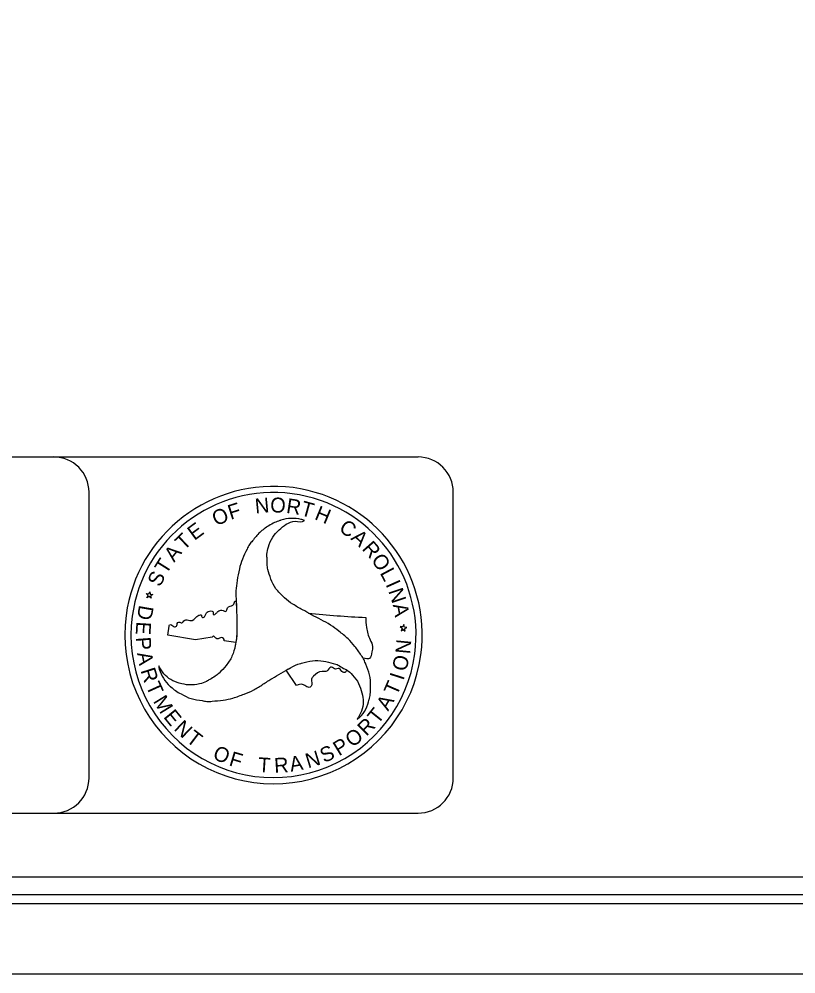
# Model space of a CAD drawing. Extents: x 2046816 to 2049224, y 578750 to 586986.
# Drawn here: x 2048068.9 to 2048289.2, y 585890.8 to 586161.6 of the extents above; entities that cross this region are included whole.
import ezdxf

# ---------------------------------------------------------------- set-up
doc = ezdxf.new("R2010")
doc.units = 0
for name, color, linetype in [('Sheet Plot Border Inside CELL', 7, 'Continuous'), ('Sheet Plot Border Outside CELL', 7, 'Continuous'), ('Sheet Title CELL', 7, 'Continuous')]:
    doc.layers.add(name, color=color, linetype=linetype)

msp = doc.modelspace()

# ---------------------------------------------------------------- linework, layer by layer
at = {"layer": 'Sheet Plot Border Inside CELL'}
msp.add_lwpolyline([(2047553.67, 585910.81), (2049219.66, 585910.81), (2049219.66, 586965.81), (2047553.67, 586965.81)], close=True, dxfattribs=at)
at = {"layer": 'Sheet Plot Border Outside CELL'}
msp.add_lwpolyline([(2049224.17, 586985.81), (2047540.67, 586985.81), (2047540.67, 585890.81), (2049224.17, 585890.81)], close=True, dxfattribs=at)
at = {"layer": 'Sheet Title CELL'}
for p, q in [((2047791.37, 586037.41), (2048182.04, 586037.41)), ((2048088.74, 585946.39), (2048088.74, 586027.41)), ((2048192.04, 585946.39), (2048192.04, 586027.41)), ((2048149.88, 586019.43), (2048149.8, 586019.35)), ((2048149.88, 586019.43), (2048149.8, 586019.35)), ((2048105.46, 585998.15), (2048104.94, 585998.66)), ((2048104.94, 585998.66), (2048105.67, 585998.56)), ((2048105.16, 585997.48), (2048105.46, 585998.15)), ((2048105.77, 585997.84), (2048105.16, 585997.48)), ((2048105.67, 585998.56), (2048105.96, 585999.2)), ((2048106.31, 585997.33), (2048105.77, 585997.84)), ((2048105.96, 585999.2), (2048106.11, 585998.5)), ((2048106.11, 585998.5), (2048106.83, 585998.41)), ((2048106.83, 585998.41), (2048106.18, 585998.05)), ((2048106.18, 585998.05), (2048106.31, 585997.33)), ((2048150.94, 585993.16), (2048150.94, 585993.16)), ((2048111.06, 585986.89), (2048111.48, 585989.39)), ((2048177.72, 585989.22), (2048177, 585989.31)), ((2048177, 585989.31), (2048177.54, 585988.81)), ((2048178.03, 585989.85), (2048177.72, 585989.22)), ((2048178.19, 585989.15), (2048178.03, 585989.85)), ((2048178.9, 585989.08), (2048178.19, 585989.15)), ((2048178.25, 585988.71), (2048178.9, 585989.08)), ((2048118.95, 585985.53), (2048111.06, 585986.89)), ((2048123.68, 585986.27), (2048118.95, 585985.53)), ((2048177.54, 585988.81), (2048177.23, 585988.14)), ((2048177.23, 585988.14), (2048177.85, 585988.49)), ((2048177.85, 585988.49), (2048178.37, 585987.99)), ((2048178.37, 585987.99), (2048178.25, 585988.71)), ((2048130.41, 585984.8), (2048127.1, 585985.28)), ((2048182.85, 585981.34), (2048182.85, 585981.34)), ((2048147.6, 585972.64), (2048144.6, 585976.91)), ((2048144.6, 585976.91), (2048144.6, 585976.91)), ((2047791.37, 585936.39), (2048182.04, 585936.39)), ((2047772.18, 585918.31), (2049192.16, 585918.31))]:
    msp.add_line(p, q, dxfattribs=at)
msp.add_lwpolyline([(2047722.16, 585913.31), (2049192.16, 585913.31)], dxfattribs=at)
for centre, radius, start, end in [((2048078.74, 586027.41), 10, 0, 90), ((2048182.04, 586027.41), 10, 360, 90), ((2048141.05, 585986.9), 42.17, 352.4211, 172.4211), ((2048141.05, 585986.9), 40.42, 352.4211, 172.4211), ((2048175.96, 586214.1), 222.36, 258.0996, 258.1992), ((2048141.05, 585986.9), 42.17, 172.4211, 352.4211), ((2048141.05, 585986.9), 40.42, 172.4211, 352.4211), ((2048175.96, 586214.1), 222.36, 263.5387, 267.7447), ((2048078.74, 585946.39), 10, 270, 360), ((2048182.04, 585946.39), 10, 270, 360)]:
    msp.add_arc(centre, radius, start, end, dxfattribs=at)
for points in [[(2048149.8, 586019.35), (2048148.89, 586019.72), (2048146.1, 586019.98), (2048143.15, 586019.45), (2048142.89, 586019.35), (2048141.37, 586018.79), (2048139.73, 586017.88), (2048137.17, 586016.03), (2048135.09, 586013.63), (2048134.24, 586012.59), (2048133.55, 586011.27), (2048132.23, 586008.44), (2048131.37, 586005.66), (2048130.74, 586002.35), (2048130.4, 585999.42), (2048130.48, 585996.37), (2048130.6, 585993.29), (2048130.65, 585990.31), (2048130.66, 585987.24), (2048130.27, 585984.25), (2048130.22, 585984), (2048129.27, 585980.88), (2048127.61, 585978.27), (2048125.64, 585976.14), (2048124.51, 585975.2), (2048122.97, 585974.29), (2048122.09, 585973.77), (2048120.07, 585973.05), (2048117.12, 585972.76), (2048114.34, 585973.3), (2048111.94, 585974.26), (2048109.95, 585975.95), (2048108.49, 585978.19)], [(2048164.82, 585963.01), (2048165.56, 585963.6), (2048167.2, 585965.89), (2048168.21, 585968.7), (2048168.29, 585968.98), (2048168.53, 585970.58), (2048168.57, 585972.48), (2048168.28, 585975.6), (2048167.2, 585978.6), (2048166.75, 585979.85), (2048165.93, 585981.14), (2048164.15, 585983.68), (2048162.18, 585985.82), (2048159.62, 585988), (2048157.24, 585989.74), (2048154.55, 585991.24), (2048151.84, 585992.66), (2048149.26, 585994.1), (2048146.55, 585995.64), (2048144.18, 585997.46), (2048144, 585997.65), (2048141.74, 586000.04), (2048140.32, 586002.79), (2048139.45, 586005.54), (2048139.23, 586006.97), (2048139.22, 586008.78), (2048139.17, 586009.82), (2048139.6, 586011.9), (2048140.82, 586014.63), (2048142.65, 586016.74), (2048144.69, 586018.32), (2048147.17, 586019.21), (2048149.8, 586019.35), (2048149.88, 586019.43)], [(2048111.48, 585989.39), (2048111.43, 585989.64), (2048111.89, 585989.85), (2048113, 585989.21), (2048113.66, 585989.64), (2048113.71, 585990.15), (2048114.24, 585990.6), (2048115.03, 585990.33), (2048115.88, 585991.16), (2048116.57, 585991.23), (2048117.99, 585991.05), (2048119.88, 585992.51), (2048120.6, 585992.51), (2048120.72, 585992.05), (2048121.14, 585991.9), (2048122.04, 585993.19), (2048122.25, 585993.37), (2048123.64, 585993.71), (2048123.95, 585993.42), (2048123.97, 585992.79), (2048124.14, 585992.64), (2048124.61, 585992.89), (2048125.29, 585993.55), (2048126.44, 585993.97), (2048127.65, 585993.66), (2048128, 585994.63), (2048129.56, 585995.41), (2048129.94, 585995.95), (2048130.09, 585996.54)], [(2048130.48, 585996.45), (2048130.48, 585996.37), (2048130.6, 585993.29), (2048130.65, 585990.31), (2048130.66, 585987.24), (2048130.4, 585984.81)], [(2048166.5, 585980.34), (2048165.93, 585981.14), (2048164.15, 585983.68), (2048162.18, 585985.82), (2048159.62, 585988), (2048157.24, 585989.74), (2048154.55, 585991.24), (2048151.84, 585992.66), (2048150.94, 585993.16)], [(2048167.2, 585991.91), (2048167.43, 585989.05), (2048168.45, 585985.57), (2048169.16, 585983.65), (2048168.93, 585982.1), (2048168.32, 585980.3), (2048166.51, 585980.35)], [(2048127.1, 585985.28), (2048126.86, 585985.93), (2048126.24, 585986.2), (2048125.32, 585985.86), (2048124.66, 585985.98), (2048124.01, 585986.6), (2048123.68, 585986.27)], [(2048108.49, 585978.19), (2048108.67, 585977.2), (2048109.83, 585974.65), (2048111.74, 585972.36), (2048111.96, 585972.2), (2048113.22, 585971.14), (2048114.83, 585970.19), (2048117.71, 585968.88), (2048120.81, 585968.31), (2048122.13, 585968.07), (2048123.69, 585968.14), (2048126.73, 585968.42), (2048129.56, 585969.04), (2048132.76, 585970.17), (2048135.44, 585971.33), (2048138.07, 585972.94), (2048140.66, 585974.6), (2048143.24, 585976.11), (2048145.9, 585977.64), (2048148.67, 585978.82), (2048148.97, 585978.89), (2048152.14, 585979.63), (2048155.2, 585979.5), (2048157.99, 585978.88), (2048159.43, 585978.37), (2048160.93, 585977.45), (2048161.89, 585976.98), (2048163.48, 585975.57), (2048165.19, 585973.16), (2048166.12, 585970.52), (2048166.49, 585967.94), (2048166.02, 585965.36), (2048164.82, 585963.01)], [(2048144.6, 585976.91), (2048145.9, 585977.64), (2048148.67, 585978.82), (2048148.97, 585978.89), (2048152.14, 585979.63), (2048155.2, 585979.5), (2048157.99, 585978.88), (2048159.43, 585978.37), (2048160.93, 585977.45), (2048161.82, 585977.01)], [(2048161.8, 585976.99), (2048161.32, 585976.31), (2048160.68, 585976.35), (2048159.7, 585977.38), (2048158.31, 585977.28), (2048157.74, 585977.72), (2048157.33, 585977.79), (2048156.19, 585976.69), (2048154.81, 585976.58), (2048152.43, 585975.27), (2048151.86, 585974.4), (2048151.75, 585972.37), (2048151.17, 585972.04), (2048150.54, 585972.23), (2048149.27, 585972.92), (2048147.6, 585972.64)]]:
    msp.add_spline(points, degree=3, dxfattribs=at)

# ---------------------------------------------------------------- texts
for s, height, rotation, p in [('F', 4.21, 17.4918, (2048128.88, 586019.55)), ('N', 4.21, 5.4049, (2048135.97, 586021.36)), ('O', 4.22, 357.9068, (2048140.06, 586021.73)), ('R', 4.21, 351.2969, (2048144.5, 586021.57)), ('T', 4.22, 344.6472, (2048148.48, 586020.96)), ('O', 4.21, 24.6387, (2048124.82, 586017.71)), ('H', 4.2, 337.5625, (2048152.45, 586019.84)), ('E', 4.19, 36.5781, (2048118.62, 586013.57)), ('C', 4.19, 325.2202, (2048159.33, 586016.58)), ('T', 4.2, 43.6937, (2048115.64, 586010.74)), ('A', 4.2, 317.7231, (2048162.76, 586014.17)), ('R', 4.2, 311.3592, (2048165.96, 586011.27)), ('A', 4.22, 50.7489, (2048112.88, 586007.37)), ('T', 4.21, 57.8012, (2048110.64, 586003.93)), ('O', 4.21, 304.2396, (2048168.61, 586008.24)), ('L', 4.19, 298.0059, (2048171.13, 586004.54)), ('S', 4.2, 64.1774, (2048108.89, 586000.33)), ('I', 4.21, 294.0166, (2048172.77, 586001.3)), ('N', 4.2, 288.3165, (2048173.57, 585999.41)), ('D', 4.21, 260.2741, (2048102.96, 585995.57)), ('A', 4.21, 280.8845, (2048174.84, 585995.49)), ('E', 4.19, 266.562, (2048102.19, 585990.8)), ('P', 4.21, 274.0944, (2048102, 585986.24)), ('N', 4.21, 84.6293, (2048179.77, 585981.4)), ('A', 4.2, 280.687, (2048102.32, 585981.76)), ('O', 4.19, 77.3812, (2048178.7, 585976.44)), ('R', 4.2, 287.7556, (2048103.3, 585976.87)), ('I', 4.22, 72.2456, (2048177.9, 585973.86)), ('T', 4.2, 294.4062, (2048104.76, 585972.47)), ('T', 4.2, 66.5957, (2048176.04, 585969.49)), ('M', 4.19, 301.6412, (2048106.79, 585968.15)), ('A', 4.21, 59.5113, (2048173.56, 585965.17)), ('E', 4.19, 309.108, (2048109.67, 585963.64)), ('T', 4.19, 51.4242, (2048170.65, 585961.39)), ('N', 4.21, 316.0795, (2048112.58, 585960.15)), ('R', 4.21, 45.3245, (2048167.41, 585958.04)), ('T', 4.2, 322.9215, (2048116.03, 585956.89)), ('O', 4.21, 38.1354, (2048163.44, 585954.87)), ('P', 4.2, 31.4434, (2048159.61, 585952.49)), ('O', 4.2, 336.2252, (2048123.53, 585951.97)), ('F', 4.2, 343.3904, (2048128.21, 585949.99)), ('N', 4.19, 17.041, (2048150.86, 585949.08)), ('S', 4.19, 24.2515, (2048155.38, 585950.56)), ('T', 4.19, 356.2997, (2048136.59, 585948.07)), ('R', 4.21, 3.2563, (2048141.35, 585947.81)), ('A', 4.19, 10.0094, (2048145.98, 585948.14))]:
    msp.add_text(s, height=height, rotation=rotation, dxfattribs=at).set_placement(p)

doc.saveas('drawing.dxf')
